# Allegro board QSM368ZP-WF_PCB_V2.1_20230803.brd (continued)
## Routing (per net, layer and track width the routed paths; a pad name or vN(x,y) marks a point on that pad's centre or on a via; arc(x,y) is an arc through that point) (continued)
N16421517: length 1.2
  TOP w0.3: R0730.2 D0706.2
N16421911: length 1.3
  TOP w0.3: D0705.2 R0708.2
N16451445: length 2.3
  BOTTOM w0.1: 38.48,21.57 R0610.2 38.4,20.6 R0622.2
N16756675: length 2.7
  BOTTOM w0.1: U0601.3 76.53,24.48 76.14,24.86 75.76,24.86 R0604.2
N16757889: length 2.3
  BOTTOM w0.2: R0614.2 69.1,24.3 69.28,24.48 69.28,25.5
N16762456: length 3.4
  BOTTOM w0.1: U0304.4 32.2,18.6 32.67,19.07 R0309.2 R0319.2 31.62,19.52 R0305.2
N16762522: length 2.1
  BOTTOM w0.1: R0308.2 R0313.2 32.2,16.02
N16784705: length 6.1
  BOTTOM w0.1: J0802.C2 70.14,18.96 69.53,19.57 69.53,21.07 69.22,21.38 D0803.3 68.25,21.38 C0806.2 67.97,21.4 R0803.2
N16784727: length 8.7
  BOTTOM w0.1: R0810.2 69.62,22.62 C0802.2 70.55,21.8 70.33,21.57 D0803.4 70.1,21.38 69.72,21 69.72,19.7 70.53,18.9 72.38,18.9 72.67,18.6 J0802.C3
N16784743: length 9.5
  BOTTOM w0.1: 73.94,17.83 73.94,18.61 73.42,19.12 70.6,19.12 69.92,19.8 69.92,20.77 70.03,20.88 D0803.5 C0804.2 R0804.1 73.03,20.88 R0808.2
N16788349: length 21.5
  TOP w0.8: J0801.P4 69.02,3.51 70.22,2.3 73.45,2.3 75.35,4.2 75.35,17.07
N16817948: length 2.2
  TOP w0.1: B1002.2 C1014.1 U1002.1
N16818791: length 2.8
  TOP w0.5: R1023.2 D1001.1 J1002.2
N16820129: length 0.8
  BOTTOM w0.23: U1001.5 12.31,63.77
N16820177: length 3.6
  BOTTOM w0.2: B1003.2 C1022.1 9.38,64.58 ; U1001.8 9.41,64.61 9.38,64.58 ; 9.38,64.58 9.38,65.42 R1016.1
N16820236: length 2.2
  BOTTOM w0.2: C1027.2 11.07,63.08 11.3,63.3 11.3,63.6 11.67,63.97 U1001.6
N16820242: length 2.7
  BOTTOM w0.2: C1022.2 10.07,63.75 10.8,63.75 11.04,63.99
  BOTTOM w0.23: U1001.7 11.04,63.99
N16820310: length 8.8
  BOTTOM w0.23: U1001.15 14.21,68.96
  BOTTOM w0.25: C1021.2 20.23,70.6 R1005.1 19.65,70.03 17.57,70.03 16.18,68.62 14.55,68.62 14.21,68.96
N16820326: length 2.2
  BOTTOM w0.23: U1001.14 13.58,70.55
  BOTTOM w0.25: 13.58,70.55 14.45,71.42 R1021.1
N16820338: length 3
  BOTTOM w0.23: U1001.13 12.94,70.82
  BOTTOM w0.25: 12.94,70.82 13.35,71.22 C1001.2 R1011.2
N16820356: length 4.1
  BOTTOM w0.23: U1001.12 12.31,70.77
  BOTTOM w0.25: 12.31,70.77 C1008.1 R1007.2 R1011.1
N16820452: length 3.7
  BOTTOM w0.23: U1001.10 11.04,68.71
  BOTTOM w0.25: 11.04,68.71 10.93,68.6 9.45,68.6 R1012.2 C1005.2
N16820458: length 4
  BOTTOM w0.23: U1001.11 11.67,70.68
  BOTTOM w0.25: R1008.1 9.7,71.38 10.05,71.03 11.32,71.03 11.67,70.68
N16820548: length 1.5
  BOTTOM w0.25: C1004.1 20.75,61.6 R1019.2
N16820558: length 0.9
  BOTTOM w0.23: U1001.4 12.94,63.73
N16820570: length 2.6
  BOTTOM w0.2: R1002.2 13.22,59.12 C1012.1
N16820612: length 2.1
  BOTTOM w0.2: C1011.1 11.43,59.2 11.62,59.4 R1020.2
N16820614: length 1.4
  BOTTOM w0.1: R1016.2 C1007.1
N16820628: length 1.9
  BOTTOM w0.25: R1008.2 8.9,73.25 9,73.35 10.45,73.35 C1017.2
N16820646: length 1.3
  BOTTOM w0.25: C1016.2 15.12,73.72 14.62,73.22
N16820759: length 3.8
  BOTTOM w0.25: C1026.2 16.05,62.05 15.28,62.83 15.28,63.5 15.03,63.75 14.46,63.75 14.21,64 U1001.2
N16820857: length 2.1
  BOTTOM w0.1: C1020.2 14.62,63.15 13.93,63.85 13.72,63.85 13.58,64 U1001.3
N16829674: length 1.5
  BOTTOM w0.1: C1111.1 U1103.2
N16829682: length 1.5
  BOTTOM w0.1: C1104.2 U1103.6
N16829803: length 1.3
  BOTTOM w0.1: U1103.10 R1120.1
N16830150: length 2.1
  BOTTOM w0.1: 102,66 102,66.5 102.2,66.7 R1134.2 R1111.2
N16830180: length 1.5
  BOTTOM w0.1: R1105.2 102.33,61.3 102.33,62.09 102.22,62.2 102,62.2
N16830190: length 7.2
  BOTTOM w0.1: Q1102.3 100.88,62.55 101.12,62.8 101.12,63.27 101.31,63.47 102,63.47 ; Q1102.3 Q1101.3 101.03,64.55 101.21,64.73 102,64.73 ; Q1102.3 R1103.1
N16831384: length 6.1
  BOTTOM w0.3: B0202.1 C0211.2 R0214.1
  BOTTOM w0.5: C0208.2 86.11,93.25 B0203.1 88.25,93.25 B0202.1
N16831443: length 4
  BOTTOM w0.3: B0204.1 B0201.1 C0212.2 77.6,92.1 78.47,91.22 U0203.5
N16831459: length 1.2
  BOTTOM w0.1: U0203.4 C0216.2
N16831535: length 4
  BOTTOM w0.4: 81.69,93.74 82.51,93.74 R0209.1 ; 81.69,93.74 R0229.1 ; 81.69,93.74 81.65,93.7 C0217.2 81.65,92.1 82.38,91.38 82.38,90.94
N16831549: length 1.2
  BOTTOM w0.1: 80.47,90.94 C0207.2
N16832505: length 2.9
  BOTTOM w0.1: C0299.2 R0212.1 R0219.2 U0205.4
N16833633:
  vias: v1(1.85,85.75) v1(1.85,85.25) v1(2.35,85.75) v1(2.35,85.25)
N16851360: length 2.8
  BOTTOM w0.4: B0501.1 B0502.1 C0526.2 U0501.5
N16851388: length 3.1
  BOTTOM w0.1: R0510.1 R0526.1 R0518.2 U0501.3
N16851406: length 1.1
  BOTTOM w0.1: C0511.1 U0501.4
N16851801: length 1.6
  BOTTOM w0.5: 64.58,71.92 66.22,71.92
N16851821: length 6
  BOTTOM w0.5: L0501.2 64,68.05 64.4,68.45 64.4,69.85 D0508.2
N16865312: length 6.5
  BOTTOM w0.1: R0949.1 R0947.2 100.2,40.52 101,41.33 101,42.02 101.9,42.92 U0902.14
N16865348: length 4.2
  BOTTOM w0.1: R0931.1 99.85,39.8 100.03,39.8 101.25,41.02 101.25,41.98 101.8,42.52 U0902.13
N16871216: length 3.4
  BOTTOM w0.1: R0913.1 108.97,39.9 108.47,40.4 108.47,40.65 108.25,40.88 108.25,41.42 107.55,42.12 U0902.39
N16979946: length 2.5
  BOTTOM w0.075: 104.62,57.12 104.25,57.12 U1102.C2
  BOTTOM w0.1: 104.62,57.12 104.72,57.12 104.8,57.2 R1107.1
  BOTTOM w0.25: R1132.1 R1107.1
N16980060: length 1
  BOTTOM w0.1: R1115.1 104.7,55.95 104.5,56.15 U1102.D3
N16980062: length 1.2
  BOTTOM w0.1: U1102.A3 103,56.35 R1130.2
N16980064: length 0.9
  BOTTOM w0.1: U1102.C3 104,55.98 103.85,55.83 R1126.2
N16980078: length 1.1
  BOTTOM w0.1: R1119.2 103,55.88 U1102.B3
N17169242: length 2.4
  TOP w0.1: v1(79.58,97) J0202.25
  BOTTOM w0.1: v1(79.58,97) R0227.1 R0226.2
N17248848: length 3
  TOP w0.3: U0502.5 C0524.2 C0528.1 21.38,98.4 B0503.1
N17248866: length 1.1
  TOP w0.1: C0514.1 U0502.4
N17269506: length 3.7
  TOP w0.1: R0515.1 13.53,93.55 14.15,94.17 14.8,94.17 15.22,93.75 15.22,92.81 U0503.3
N17270599: length 1.7
  TOP w0.3: R0513.2 C0535.2 16.1,92.03
N17274420: length 1.3
  TOP w0.1: v1(28.88,98.53) 29.07,98.33 J0501.7
  BOTTOM w0.1: v1(28.88,98.53) R0528.1
N17308117: length 5.8
  TOP w0.1: S1202.2 102.75,94.4 103.58,93.58 D1201.2 R1208.2
N17310824: length 1
  TOP w0.5: R0116.2 D0102.2
N17312479: length 2.6
  BOTTOM w0.1: R0104.1 R0101.1 27.55,83.58 27.55,84.12 27.7,84.28 27.98,84.28
N17312557: length 0.9
  BOTTOM w0.1: C0111.2 27.98,83.78
N17312561: length 2.7
  BOTTOM w0.1: 30.18,84.1 30.32,84.25 ; 30.18,84.1 30.18,84.35 ; 30.18,84.1 30.18,83.65 29.38,82.85 C0111.1 ; 30.18,84.1 30.07,84.2
N17312853: length 1.8
  BOTTOM w0.1: R0115.2 R0108.2 27.98,84.78
N17316601: length 3.6
  BOTTOM w0.1: R0166.1 R0113.1 R0103.2 51.38,84.55 51.38,85.15 51.48,85.25 U0103.5
N17316611: length 1.2
  BOTTOM w0.1: C0113.2 51.85,84.5 U0103.4
N17316621: length 3.5
  BOTTOM w0.1: 53.42,83.83 53.48,83.83 54,84.35 54,85.5 54.88,86.38 55.08,86.38 L0101.1
N17316661: length 1.9
  BOTTOM w0.1: R0105.2 R0114.1 U0103.6
N17321443: length 3
  BOTTOM w0.1: U0104.5 35.12,66.35 34.95,66.53 34.42,66.53 R0110.2 R0117.1
N17321453: length 0.9
  BOTTOM w0.1: U0104.4 C0114.2
N17321455: length 2.7
  BOTTOM w0.1: C0114.1 34.2,64.65 34.2,64.4 34.48,64.12 35.02,64.12 35.6,63.55
N17321503: length 1.9
  BOTTOM w0.1: R0102.2 R0112.1 U0104.6
N17391886: length 3.7
  BOTTOM w0.1: 35.83,49.92 35.83,50.23 36.08,50.48 R0620.1 R0615.2 36.92,50.45 37.02,50.35 37.92,50.35 38.1,50.17 U0604.5
N17391896: length 0.9
  BOTTOM w0.1: U0604.4 36.67,49.92
N17391898: length 2.5
  BOTTOM w0.1: 38.02,47.05 36.67,48.4 C0618.1
N17391938: length 1.7
  BOTTOM w0.1: U0604.6 38.62,49.95 R0613.1 R0606.2
N17593444: length 2.7
  BOTTOM w0.1: U1204.1 C1203.2 R1202.2 R1205.2
N17594281: length 1.2
  BOTTOM w0.1: U1204.9 C1204.2
N17594510: length 3.1
  BOTTOM w0.1: U1204.8 83.53,70.2 C1202.2 R1210.2 R1211.2
N17654307: length 5.4
  TOP w0.1: J0501.5 29.88,98.62 30.4,99.15 33.1,99.15 TP0502.1
N17980948: length 3.1
  BOTTOM w0.1: U0701.5 68.53,32.97 68.39,32.97 68.08,32.66 68.08,32.65 R0725.2 R0726.2 R0723.1
N17980958: length 1.3
  BOTTOM w0.1: C0714.2 69.03,32.23 68.83,32.42 U0701.4
N17980968: length 2.8
  BOTTOM w0.1: L0701.1 72.1,31.9 71.65,31.45 C0714.1
N17981000: length 2
  BOTTOM w0.1: R0717.1 R0718.2 67.75,33.83 68.15,33.42 U0701.6
N18035182: length 1.5
  BOTTOM w0.3: L0901.2 R0988.1
N18073365: length 2.7
  TOP w0.5: R1010.2 D1003.1 22.68,11.41 J1002.3
N18075719: length 5.7
  TOP w0.1: J1002.4 21.18,12.09 20.45,12.82 19.9,12.82 19.8,12.93 D1004.1 R1014.2
N18080454: length 3.8
  TOP w0.25: R1003.1 C1015.2 C1099.2 16.52,90.2 D1002.1 16.57,88.91 U1002.4
N18191565: length 8.2
  BOTTOM w0.1: R1117.2 100.97,68.03 98.35,65.4 R1121.2 Q1101.1
N18198024: length 1
  BOTTOM w0.1: R1125.1 Q1102.1
N18247329: length 11.2
  BOTTOM w0.3: R0426.2 9.22,17.25 R0420.2 7.55,17.6 7.78,17.82 7.78,18.32 7.12,18.98 5.24,18.98 4.85,19.36 4.85,22.15 6.08,23.38 D0402.1
N18365015: length 3.9
  TOP w0.5: D0405.1 C0412.1 C0408.1 R0402.2
N18366438: length 3.3
  BOTTOM w0.1: C0405.1 R0407.2 63.8,91.08 Q0401.1 64.35,91.88 64.83,92.35 Q0402.3
N18378711: length 3.7
  BOTTOM w0.1: D0507.3 18.2,33.4 18.05,33.55 C0517.1 R0529.2 16.18,33.55 15.93,33.3 Q0501.1
N18380308: length 6.4
  BOTTOM w0.1: R0503.2 6.28,44.17 5.8,43.7 C0516.1 ; R0503.2 7.47,44.17 7.58,44.27 Q0502.1 ; R0503.2 6.72,43.02 6.08,42.38 D0503.3
N18382144: length 2.2
  BOTTOM w0.1: 11.72,42.88 13.72,42.88 TP0503.1
N18382149: length 2.5
  BOTTOM w0.1: 9.32,53.38 8.03,53.38 TP0501.1
N18582530: length 241.3
  TOP w0.1: v1(98.6,69.53) 98.6,68.62 99.33,67.9 99.33,60 100.77,58.55 108.95,58.55 113.17,54.33 115.55,54.33 117.44,52.44 117.44,49.61 118.47,48.58 118.47,31.08 115.91,28.51 115.91,26.84 114.1,25.02 114.1,21.7 118.92,16.88 118.92,2.85 117.15,1.07 81.33,1.07 v1(80.05,2.35) ; U1301.171 23.38,47.48 v1(22.9,47.95) ; v1(60.3,2.38) 59.7,2.98 59.33,2.98 57.27,5.03 42.1,5.03 39.49,7.64 v1(39.49,7.94)
  INNER LAYER 3 w0.1: v1(22.9,47.95) 22.7,47.95 22.43,47.67 22.43,45.33 25.43,42.33 25.43,32.6 24.43,31.6 24.43,18.98 28.82,14.57 29.6,14.57 32.65,11.53 36.52,11.53 39.08,8.97 39.08,8.35 v1(39.49,7.94) ; v1(80.05,2.35) 79.42,2.98 60.58,2.98 60.3,2.7 v1(60.3,2.38) ; v1(82.03,73.65) 83.67,75.3 86.65,75.3 92.08,69.88 98.25,69.88 v1(98.6,69.53)
  BOTTOM w0.2: v1(82.03,73.65) R1301.1
N18603622: length 2.9
  TOP w0.1: U1301.231 39.75,32.27 39.95,32.08 40.08,32.08 41.38,30.77 41.42,30.77 TP1401.1
N18618933: length 1.1
  BOTTOM w0.2: R0416.2 D0401.1
N18646162: length 6.5
  TOP w0.1: TP1403.1 42.33,31.12 41.77,31.68 41.12,31.68 40.55,32.25 U1301.232
N18646180: length 6.2
  TOP w0.1: U1301.227 38.95,32.23 39.52,31.65 39.85,31.65 40.5,31 TP1404.1
N18646198: length 5.4
  TOP w0.1: TP1405.1 38.48,31.8 37.75,31.8 37.35,32.2 U1301.222
N18646284: length 4
  TOP w0.1: R1457.2 TP1402.1 36.55,32.23 U1301.221
N18671521: length 2.8
  BOTTOM w0.1: C0211.1 R0214.2 89.28,91 89.3,90.97 R0224.2 U0204.1
N18920153: length 3.4
  TOP w0.1: U1301.234 v1(42.15,37.7)
  BOTTOM w0.1: v1(42.15,37.7) 42.25,37.8 43.12,37.8 43.58,38.25 43.58,39.1
N18932423: length 1.7
  TOP w0.1: 38.92,29.52 38.92,27.82
N19051361: length 1.7
  BOTTOM w0.1: U1103.4 106.8,78.88 106.35,79.33 C1113.1
N19051366: length 1.6
  BOTTOM w0.1: C1113.2 107.25,79.3 107.45,79.1 U1103.5
N19051381: length 0.9
  BOTTOM w0.1: C1105.1 U1103.1
N19051390: length 3
  BOTTOM w0.1: U1103.3 106.15,77.4 106,77.25 C1105.2
N19051717: length 2.6
  BOTTOM w0.1: U1103.9 109.4,71.58 109.2,71.38 109.2,70.33 109.08,70.2 R1133.1
N19139644: length 3.2
  TOP w0.4: R0325.1 D0353.1 37.33,5.9 36.94,5.51 36.94,4.62
N19156624: length 2.7
  BOTTOM w0.1: R1155.2 R1156.1 101.83,58.08 102.1,57.8 102.3,57.8 102.72,57.38 U1102.A1
N19156735: length 2.4
  BOTTOM w0.1: R1157.2 R1158.1 104.4,58.1 104.17,57.88 104,57.88 U1102.B1
N19156807: length 2.7
  BOTTOM w0.1: U1102.C1 104.47,57.85 105.03,57.85 105.25,58.08 R1159.2 R1160.1
N19156822: length 3.7
  BOTTOM w0.1: U1102.D1 104.78,57.65 105.12,57.65 105.3,57.83 106.53,57.83 R1162.1 R1161.2
N19197680: length 2.5
  TOP w0.1: v1(41.25,38.58) U1301.229
  BOTTOM w0.1: v1(41.25,38.58) 41.85,38.58 41.88,38.6 R1467.1 R1466.1
N19332658: length 2.7
  TOP w0.1: J0701.17 TP0702.1
N19332747: length 2.3
  TOP w0.1: J0701.1 82.67,27.35 82.67,26.12 TP0703.1
N19347845: length 1.7
  BOTTOM w0.1: U0702.13 R0731.1
N19347847: length 1.8
  BOTTOM w0.1: R0729.1 95.4,59.6 95.2,59.4 U0702.12
N19347865: length 2.6
  BOTTOM w0.1: U0702.8 95.8,62 R0727.2 R0705.1
N19347930: length 2
  BOTTOM w0.1: U0702.2 87.45,58.75 86.9,58.2 R0713.2
N19349212: length 2
  BOTTOM w0.1: R0720.2 87.42,59.4 U0702.3
N19352428: length 1.7
  TOP w0.1: R0724.2 103.17,26.27 103.28,26.38 J0701.45
N19352448: length 1.7
  TOP w0.1: J0701.47 104.08,26.32 104.03,26.27 R0703.2
N19352470: length 1.7
  TOP w0.1: J0701.49 R0710.2
N19352490: length 1.7
  TOP w0.1: R0714.2 105.72,26.27 105.67,26.32 J0701.51
N19352717: length 1.8
  BOTTOM w0.1: R0711.1 C0706.2 D0703.3
N19354367: length 2.4
  TOP w0.1: R0701.2 94.47,25.18 J0701.23
N19354450: length 3.4
  TOP w0.1: J0701.31 97.67,25.12 97.28,24.73 R0704.2
N19356842: length 2.5
  TOP w0.1: J0701.33 R0706.2
N19357290: length 1.9
  TOP w0.3: J0701.24 R0728.1
N19357904: length 14
  TOP w0.1: J0701.32 98.08,30.6 v1(98.03,30.55) ; v1(93.53,24.95) TP0701.1
  INNER LAYER 3 w0.1: v1(93.53,24.95) 93.53,26.8 97.28,30.55 v1(98.03,30.55)
N19358667: length 2.4
  BOTTOM w0.1: R0721.2 87.28,60.92 87.53,60.67 87.53,60.3 87.78,60.05 U0702.4
N19358768: length 1.9
  BOTTOM w0.1: R0733.1 95.67,60.45 95.28,60.05 U0702.11
N19359275: length 9.2
  TOP w0.1: R0715.1 110.6,37.55 104.7,37.55 103.67,36.52 J0701.46
N19367635: length 1.9
  BOTTOM w0.1: U0702.10 95.35,60.7 R0722.1
N193479154: length 4.8
  BOTTOM w0.1: U0702.5 89.85,60.7 90.08,60.92 90.08,62.48 89.22,63.33 R0712.2

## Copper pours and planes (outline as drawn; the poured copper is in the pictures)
AVDD33_A on BOTTOM: 106.88,41.62 107.33,41.62 107.58,41.38 107.58,40.23 108.08,40.23 108.12,40.27 108.12,40.77 108.04,40.86 108.04,41.41 107.62,41.83 106.78,41.83 106.78,41.73
DVDDRG_A on BOTTOM: 105.78,46.02 105.78,46.45 105.85,46.52 105.85,47.45 105.53,47.77 105.38,47.77 105.22,47.62 105.22,47.3 105.53,47 105.53,46.35 105.58,46.3 105.58,46.05 105.6,46.02
VBATT on TOP: 15.88,86.12 17.45,86.12 17.7,86.38 18.35,86.38 18.52,86.2 18.52,84.7 18.4,84.58 17.73,84.58 17.48,84.83 15.88,84.83
VBATT on TOP: 75.12,85.88 75.72,85.28 75.72,84.7 75.25,84.22 74.72,84.22 73.88,85.08 73.88,85.4 74.35,85.88
VBATT on TOP: 46.58,77.28 50.2,77.28 51.75,78.83 51.75,79.95 51.42,80.28 48.08,80.28 45.88,82.47 37.42,82.47 35.52,80.58 35.52,79.15 35.62,79.05 36.48,79.05 36.8,79.38 44.48,79.38
VBATT on TOP: 69.28,84.55 66.83,84.55 65.95,83.67 65.95,82.75 67.2,81.5 68.03,81.5 69.28,82.75
VBATT on TOP: 15.2,92.17 15.03,92.17 14.9,92.3 13.28,92.3 13.15,92.17 13.15,91.85 13.25,91.75 15.22,91.75 15.35,91.88 15.35,92.03
VBATT on TOP: 61.08,77.85 58.92,77.85 58.67,78.1 58.67,80.12 59.38,80.83 61,80.83 61.42,80.4 61.42,78.2
VBATT on BOTTOM: 87.97,89.6 88.83,89.6 89.03,89.8 89.55,89.8 89.55,88.67 88.75,88.67 88.75,89.28 88.72,89.3 87.97,89.3
VBATT on BOTTOM: 31,80.58 36.42,80.58 36.52,80.47 36.52,78.15 35.6,77.22 31,77.22 30.88,77.35 30.88,80.45
VBATT on BOTTOM: 62.05,70.35 61.45,70.35 61.05,70.75 61.05,71.75 60.38,71.75 60.35,71.72 60.35,70.78 59.98,70.4 59.17,70.4 59.17,69.7 62.05,69.7
VBATT on BOTTOM: 21.07,83.62 21.07,80.9 24.75,77.22 27,77.22 27.95,78.17 27.95,78.6 22.93,83.62
VBATT on BOTTOM: 50.3,79.9 50.3,77.62 50.65,77.28 52.15,77.28 52.62,77.75 52.62,79.95 52.3,80.28 50.67,80.28
VBATT on BOTTOM: 59.67,79.83 59.67,78.03 58.77,77.12 58.1,77.12 57.5,77.72 57.5,80.05 57.73,80.28 59.23,80.28
VBATT on BOTTOM: 75.12,85.88 75.85,85.15 75.85,84.7 75.42,84.28 74.5,84.28 74.05,84.72 74.05,85.3 74.62,85.88
VBATT_M on TOP: 15.88,83.33 16.15,83.6 19.77,83.6 19.93,83.45 19.93,82.12 19.55,81.75 17.75,81.75 17.48,82.03 15.88,82.03
VBATT_M on TOP: 23.45,54.23 24.55,54.23 25.35,55.02 26.45,55.02 27.25,54.23 28.25,54.23 28.25,51.92 27.15,51.92 26.35,51.12 25.25,51.12 24.45,50.33 23.45,50.33
VBATT_M on BOTTOM: 24.27,52.08 22.52,53.83 22.52,61.27 22.55,61.3 22.55,64.17 22.88,64.5 22.88,67.8 22.55,68.12 22.55,74.25 17.85,78.95 17.85,80.88 18.45,81.47 18.45,83.28 19.02,83.85 19.85,83.85 20.45,83.25 20.45,80.88 25.85,75.47 25.85,68.03 26.18,67.7 26.18,64.45 25.75,64.03 25.75,61.45 25.65,61.35 25.65,52.2 25.52,52.08
VBUS_USB_HOST1 on TOP: 39.95,16.5 39.95,13.25 41.02,13.25 41.25,13.03 41.62,13.03 41.62,13.55 41.1,14.07 40.88,14.07 40.8,14.15 40.8,16.23 41.08,16.5 41.08,16.85 40.9,17.02 40.48,17.02
VBUS_USB_HOST1 on BOTTOM: 40.1,21.98 42.15,21.98 42.17,21.95 42.17,19.48 42.05,19.35 40.12,19.35 40.1,19.38
VBUS_USB_HOST2 on TOP: 80.42,17.75 80.42,19.52 79.8,20.15 79.3,20.15 78.83,20.62 78.83,21.15 79,21.32 80.8,21.32 82.15,19.98 82.92,19.98 82.92,17.98 82.83,17.98 82.6,17.75
VBUS_USB_HOST2 on BOTTOM: 78.15,25.95 79.85,25.95 80.15,25.65 80.15,23.8 79.7,23.35 78.15,23.35
VBUS_USB_HOST2 on BOTTOM: 78.95,21.45 79.9,21.45 80.1,21.25 80.1,20.93 79.65,20.48 79.05,20.48 78.8,20.73 78.8,21.3
VBUS_USB_HOST3 on TOP: 80.65,12.72 80.65,15.9 81.62,15.9 81.62,13.03 81.33,12.72
VBUS_USB_HOST3 on TOP: 73.42,23.35 72.65,23.35 72.42,23.57 72.42,23.98 72.7,24.25 73.38,24.25 73.6,24.02 73.6,23.52
VBUS_USB_HOST3 on BOTTOM: 70.9,25.9 72.8,25.9 72.95,25.75 72.95,24.25 73.45,23.75 73.45,23.5 73.3,23.35 70.9,23.35
VCC3V3_SD on TOP: 50.5,35.27 50.5,34.23 50.55,34.17 50.83,34.17 50.95,34.05 50.95,33.8 50.83,33.67 50.05,33.67 49.8,33.92 49.8,35.27
VCC3V3_SD on INNER LAYER 2: 50.45,33.3 50.95,33.8 50.95,34.05 50.83,34.17 50.08,34.17 49.8,33.9 49.8,33.48 49.98,33.3
VCC5V0_SYS on TOP: 23.45,46.23 24.45,46.23 24.68,46.45 25,46.45 25.25,46.2 25.43,46.2 25.57,46.05 25.57,45.77 25.4,45.6 25.18,45.6 25,45.42 24.55,45.42 24.45,45.52 23.45,45.52
VCC5V0_SYS on BOTTOM: 26.32,46.17 25.77,46.17 25.5,46.45 24.75,46.45 24.62,46.33 24.62,45.52 24.85,45.3 26,45.3 26.32,45.62
VCC5V0_USB on TOP: 70.38,27.1 70.95,27.68 71.85,27.68 72.4,27.12 72.4,26.57 71.7,25.88 70.6,25.88 70.38,26.1
VCC5V0_USB on TOP, BOTTOM: 63.02,27.38 64.45,27.38 64.55,27.27 64.55,26.15 64.28,25.88 62.95,25.88 62.65,26.18 62.65,27
VCC5V0_USB on BOTTOM: 30.62,45.27 30.62,37.23 33.65,37.23 33.65,46.38 31.73,46.38
VCC5V0_USB on BOTTOM: 42.17,22.75 40.83,22.75 40.1,23.48 40.1,24.3 42.05,24.3 42.17,24.18
VCC5V0_USB on BOTTOM: 34.65,26 34.65,30.82 34.95,31.12 37.3,31.12 37.7,30.73 37.7,26.57 37.12,26
VCC5V0_USB on BOTTOM: 35.85,17 34.73,17 33.83,17.9 33.83,18.7 35.62,18.7 35.85,18.48
VCC5V0_USB on BOTTOM: 70.9,28.2 72.78,28.2 72.9,28.07 72.9,26.5 71.22,26.5 70.9,26.82
VCC5V0_USB on BOTTOM: 78.15,28.25 80.15,28.25 80.15,26.43 79.17,26.43 78.15,27.45
DC12V on TOP: 3.17,44.7 3.42,44.7 4.05,45.33 4.05,45.58 3.6,46.02 3.5,46.02 3.05,45.58 3.05,44.83
DC12V on TOP: 9.8,82.83 10.95,82.83 11.07,82.7 11.07,82.47 10.28,81.67 9.75,81.67 9.55,81.88 9.55,82.58
DC12V on TOP: 39.83,88.03 43.58,88.03 44.48,87.12 49.1,87.12 49.7,87.72 49.7,87.9 49.83,88.03 51.1,88.03 51.25,87.88 51.25,84.65 50.58,83.97 39.83,83.97
DC12V on TOP: 26,88.6 23.25,88.6 22.4,87.75 22.4,85.88 24.27,84 26.62,84 26.62,87.97
DC12V on BOTTOM: 38.45,48.8 38.85,48.8 39.62,49.58 39.62,51.8 40.08,52.25 42.17,52.25 42.17,49.77 42.58,49.38 42.58,48 39.67,48 39.48,48.2 38.55,48.2 38.45,48.3
DC12V on BOTTOM: 54.02,88.3 54.02,86.2 53.42,85.6 52.98,85.6 52.38,86.2 49.92,86.2 49.7,86.42 49.7,88.25 49.75,88.3
DC12V on BOTTOM: 69.58,33.65 68.8,34.42 64.33,34.42 63.27,33.38 61.2,33.38 61.2,35.55 62.27,36.62 68.92,36.62 70.53,35.02 70.53,33.65 70.15,33.27 69.7,33.27 69.58,33.4
DC12V on BOTTOM: 39.38,63.85 36.1,63.85 35.48,64.47 35.48,64.92 36,64.92 36.08,65 36.08,70.1 39.08,70.1 39.08,65.7 39.38,65.4
DC12V on BOTTOM: 39.33,40.45 37.12,40.45 36.27,39.6 36.27,35.83 38.08,34.02 38.08,30.12 40.1,28.1 43.3,28.1 43.3,31.1 42.48,31.1 41.55,32.02 41.55,34.3 41,34.85 41,35.2 39.85,36.35 39.85,39.92
DC12V on BOTTOM: 4,46.85 5.17,46.85 5.28,46.95 6.08,46.95 6.08,45.67 6.4,45.35 7,45.35 7,44.8 3.65,44.8 3.55,44.7 3.17,44.7 3.05,44.83 3.05,45.58 3.17,45.7 3.65,45.7 4,46.05
DC12V on BOTTOM: 40,74.9 40,84.75 40.4,85.15 42.65,85.15 43,84.8 43,74.9
DC12V on BOTTOM: 14.72,69.12 14.72,70.53 15.38,70.53 15.85,71 15.85,76.9 14.8,77.95 14.8,78.68 14.57,78.9 6.22,78.9 6.22,83.6 7.05,84.42 11.62,84.42 15.53,88.33 24.32,88.33 25.55,87.1 29.55,87.1 29.55,84.62 29.1,84.62 28.27,85.45 25.62,85.45 24.6,84.42 18.23,84.42 17.32,83.53 17.32,78.62 17.95,78 17.95,70.5 17.35,70.5 15.97,69.12
DC12V on BOTTOM: 40.7,64.08 40.7,62.58 42.2,61.08 42.2,59.85 41.48,59.12 39.62,59.12 37.9,60.85 37.9,63.17 36.73,64.35 36.73,65.17 36.92,65.38 39.4,65.38
EDP_VDDIN on BOTTOM: 8.53,39.58 10.43,39.58 10.93,40.08 12.55,40.08 14.11,38.51 14.11,36.41 14.78,35.75 14.9,35.75 14.9,34.83 14.55,34.48 12.62,34.48 12.57,34.42 11.82,34.42 11.8,34.45 11.8,35.45 11.9,35.45 12.28,35.83 12.28,37.77 11.9,38.15 8.75,38.15 8.53,38.38
EDP_VLED on BOTTOM: 8.65,52.58 7.53,52.58 7.05,52.1 7.05,49.35 6.65,48.95 4.6,48.95 4,48.35 4,47.65 4.8,47.65 4.8,47.92 4.92,48.05 7.05,48.05 7.95,48.95 7.95,51.6 8.65,52.3
ETH_3V3_A on BOTTOM: 89.95,43.62 92.5,43.62 92.5,43.08 91.8,43.08 91.65,42.92 91.65,40.83 90.83,40.83 89.95,41.7
LVDS_VDD3V3 on BOTTOM: 62.33,92.45 62.88,92.45 62.98,92.35 63.92,92.35 63.92,92.8 63.08,92.8 62.88,93 62.33,93
MODULE_4G_3V5 on TOP: 83.17,36.75 83.17,34.65 83.62,34.2 83.62,32.98 83.58,32.92 80.97,32.92 80.65,33.25 80.65,34.38 80.97,34.7 82.53,34.7 82.58,34.75 82.58,36.75
MODULE_4G_3V5 on TOP: 101.85,24.73 101.9,24.73 102.2,25.02 102.2,26.2 101.97,26.43 100.6,26.43 100.58,26.4 100.58,24.75 100.65,24.68 101.8,24.68
MODULE_4G_3V5 on BOTTOM: 76.72,30.7 76.72,36.48 77.35,37.1 83.58,37.1 84.55,36.12 84.55,31.9 84.53,31.88 83.28,31.88 82.2,32.95 80.72,32.95 78.47,30.7
REGOUT_A on BOTTOM: 106.85,48.42 106.85,47.3 106.55,47 106.55,46.52 106.38,46.35 106.38,46.17 106.58,46.17 106.6,46.2 107.12,46.2 108.65,47.73 108.65,48.42
SPK_OUT_LN on BOTTOM: 8.53,63.4 8.53,61.9 8.45,61.83 7.62,61.83 7.62,63.4
SPK_OUT_LP on BOTTOM: 10.6,60.77 8.75,60.77 8.75,60.08 10.6,60.08
USB_VBUS on TOP: 35.17,5.35 34.55,5.35 34.38,5.53 33.77,5.53 33.42,5.88 33.42,6.55 33.58,6.7 34.1,6.7 34.1,6.2 34.2,6.1 34.73,6.1 35.17,5.65
USB_VBUS on TOP: 33.1,13.97 33.1,11.12 33.12,11.1 34.48,11.1 35.17,11.8 35.17,14.25 35,14.43 33.55,14.43
USB_VBUS on TOP: 40.02,12.93 40.88,12.93 41.52,12.28 41.52,11.68 40.62,10.78 38.88,10.78 38.6,11.05 38.6,11.47 38.8,11.68 39.5,11.68 39.9,12.07 39.9,12.8
USB_VBUS on BOTTOM: 33.83,16.43 35.65,16.43 35.85,16.23 35.85,14.5 35.2,13.85 33.3,13.85 33.3,15.22 33.83,15.75
VDC_3V3 on TOP: 78.97,5.5 77.95,5.5 77.7,5.25 77.7,4.8 78,4.5 78.97,4.5 79.12,4.65 79.12,5.35
VDC_3V3 on TOP: 69.75,88.35 67.92,88.35 67.92,89.05 69.7,89.05 69.75,89
VDC_3V3 on TOP: 101.2,74.85 108.83,74.85 110.08,73.6 108.3,71.83 101.05,71.83 100.9,71.97 100.9,74.55
VDC_3V3 on TOP: 93.5,40.2 94.08,40.2 94.25,40.38 94.25,41.08 93.95,41.38 93.3,41.38 92.95,41.02 92.95,40.75
VDC_3V3 on TOP: 109.78,60.62 111.33,60.62 111.83,60.12 111.83,58.23 111.42,57.83 110.45,57.83 109.78,58.5
VDC_3V3 on TOP: 59.6,81.58 59.6,89.45 60.17,90.03 62.02,90.03 62.6,89.45 62.6,82.38 61.5,81.28 59.9,81.28
VDC_3V3 on TOP: 100.22,74.1 100.22,72.6 100.97,71.85 102.3,71.85 102.65,72.2 102.65,74.55 102.35,74.85 100.97,74.85
VDC_3V3 on TOP: 105.17,52.58 105.6,52.58 105.88,52.3 105.88,51.62 105.7,51.45 105.08,51.45 104.88,51.65 104.88,52.27
VDC_3V3 on TOP: 112.3,66.33 109.67,66.33 109.3,65.95 109.3,64.83 109.97,64.15 112.3,64.15
VDC_3V3 on TOP: 117.38,2.92 117.95,2.92 118.08,2.8 118.08,2.23 117.78,1.93 117.3,1.93 117.05,2.17 117.05,2.6
VDC_3V3 on BOTTOM: 59.8,84.78 59.8,88.58 57.65,90.72 57.65,91.95 61.2,91.95 61.2,92.1 62,92.1 62,90.75 62.27,90.47 62.27,85.33 61.73,84.78
VDC_3V3 on BOTTOM: 101.4,74.38 102.4,74.38 102.55,74.22 102.55,73.03 102.4,72.88 101.42,72.88 101.05,73.25 101.05,74.03
VDC_3V3 on BOTTOM: 92.15,41.83 92.15,40.9 92.42,40.9 92.95,40.38 93.22,40.38 93.42,40.17 94.1,40.17 94.2,40.27 94.2,40.58 92.95,41.83
VDC_3V3 on INNER LAYER 3: 117.33,2.02 117.88,2.02 118.22,2.38 118.22,2.83 117.95,3.1 117.55,3.1 117.22,2.77 117.22,2.12
VDC_3V3 on INNER LAYER 3: 101.6,74.38 102.53,74.38 102.65,74.25 102.65,73 102.53,72.88 101.53,72.88 101.17,73.22 101.17,73.95
VDC_3V3 on INNER LAYER 3: 118.22,50.4 118.62,50.4 118.9,50.12 118.9,49.45 118.75,49.3 118.08,49.3 117.9,49.48 117.9,50.08
VDC_3V3 on INNER LAYER 3: 59.8,82.1 59.8,80.47 60.73,79.55 62.05,79.55 62.8,80.3 62.8,81.72 61.98,82.55 60.25,82.55
VDC_3V3 on INNER LAYER 3: 110.53,58.77 111.25,58.77 111.58,58.45 111.58,58.08 111.28,57.77 110.65,57.77 110.38,58.05 110.38,58.62
VDC_3V3 on INNER LAYER 3: 105.15,51.58 105.58,51.58 105.9,51.9 105.9,52.35 105.62,52.62 105.15,52.62 104.9,52.38 104.9,51.83
VDC_5V on BOTTOM: 8.28,26.9 8.28,23 8.3,22.98 10.05,22.98 10.22,23.15 10.22,26.55 9.88,26.9
VDC_5V on BOTTOM: 33.6,58.05 37.02,58.05 37.62,57.45 37.62,55.05 37.35,54.77 33.6,54.77
VDC_5V on BOTTOM: 29.15,46.65 27.15,46.65 26.68,46.17 26.68,45.48 27,45.15 28.5,45.15 29.15,45.8
N16788349 on TOP: 75.75,20.88 75.75,16.62 75.6,16.48 74.95,16.48 74.95,20.82 75,20.88
N16820129 on BOTTOM: 9.7,62.27 10.88,62.27 10.97,62.38 11.38,62.38 11.78,62.77 11.78,63.48 12.12,63.83 12.12,63.92 12.2,64 12.4,64 12.47,63.92 12.47,62.5 12.28,62.3 12.28,61.48 9.8,61.48 9.7,61.58
N16820177 on BOTTOM: 10.53,64 10.53,65.4 9.8,66.12 8.47,66.12 8.45,66.1 8.45,65.35 8,64.9 7.62,64.9 7.62,64.2 7.83,64
N16820536 on BOTTOM: 14.72,64 14.72,65.22 15.65,65.22 15.82,65.05 15.82,64.45 17.7,62.58 19.07,62.58 19.07,61.27 17.2,61.27 16.68,61.8 16.68,62.25 16.45,62.48 16.23,62.48 15.55,63.15 15.55,63.55 15.1,64
N16820558 on BOTTOM: 12.82,64 13.05,64 13.47,63.58 13.47,62.85 14.15,62.17 15.15,62.17 15.15,61.58 15.05,61.48 12.6,61.48 12.6,62.38 12.78,62.55 12.78,63.85 12.82,63.9
N16831384 on BOTTOM: 86.03,90.35 84.17,90.35 84.17,92.22 85.6,92.22 86.22,91.6 86.22,90.8 86.42,90.6 87.17,90.6 87.17,90.3 86.08,90.3
N16833633 on BOTTOM: 4.7,79.25 4.7,84.37 3.95,85.07 3.95,90.42 3.02,91.35 1.82,91.35 0.93,90.45 0.93,79.92 1.6,79.25
N16833633 on INNER LAYER 3: 1.38,91.08 3.3,91.08 4.05,90.33 4.05,84.97 3.83,84.75 1.77,84.75 0.93,85.6 0.93,90.62
N16851801 on BOTTOM: 67.8,71.47 65.55,71.47 65.55,72.35 65.58,72.38 66.88,72.38 67.17,72.67 67.17,72.88 67.8,72.88
N16851821 on BOTTOM: 63.1,70.35 63.95,70.35 64.03,70.42 65.12,70.42 65.12,69.62 63.17,69.62 63.1,69.7
N17312561 on BOTTOM: 29.1,84.42 29.8,84.42 31.57,86.2 34.92,86.2 34.95,86.17 34.95,84.35 31.45,84.35 31.23,84.12 29.1,84.12
N17316621 on BOTTOM: 52.98,85.4 53.42,85.4 54.25,86.22 54.25,88.17 56.1,88.17 56.1,84.78 53.75,84.78 53.42,85.1 52.98,85.1
N17321455 on BOTTOM: 34.98,64.92 34.98,64.33 34.48,63.83 34.48,63.8 34.27,63.6 33.6,63.6 33.6,61.75 33.62,61.73 36.9,61.73 36.98,61.8 36.98,63.65 36.1,63.65 35.27,64.47 35.27,64.92
N17391898 on BOTTOM: 37.95,48.8 37.95,48.15 37.75,47.95 37.33,47.95 37.33,42.98 39.2,42.98 39.2,47.83 39.08,47.95 38.45,47.95 38.25,48.15 38.25,48.8
N17980968 on BOTTOM: 70.9,34.08 70.67,33.85 70.67,33.48 70.28,33.08 69.7,33.08 69.7,32.77 70.22,32.77 71.17,31.82 71.17,30.68 73.03,30.68 73.03,34.08
N18035182 on BOTTOM: 106.85,49.23 108.65,49.23 108.65,50.12 108.58,50.2 108.58,51.85 108.75,52.02 109.3,52.02 109.35,52.08 109.35,52.67 107.78,52.67 107.78,50.27 107.53,50.02 106.95,50.02 106.85,49.92
N18365015 on TOP: 72.95,88.85 73.05,88.85 73.5,89.3 73.5,92.28 73.67,92.45 74.22,92.45 74.4,92.28 74.4,89.3 74.85,88.85 74.95,88.85 74.95,87.75 72.95,87.75
N18365073 on TOP: 70.8,88.35 70.8,89.9 70.9,90 73,90 73,89.3 72.9,89.3 72.45,88.85 72.45,87.75 71.65,87.75 71.05,88.35
N18670938 on BOTTOM: 87.17,89.6 86.08,89.6 86.03,89.55 84.17,89.55 84.17,88.85 85.97,88.85 86.42,89.3 87.17,89.3

Small or netless copper shapes (teardrops, artwork), in the pictures only: 8 on TOP, 5 on BOTTOM, 2 on INNER LAYER 2, 4 on INNER LAYER 3

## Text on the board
BOTTOM: QSM368ZP-WF_V2.1_BOTTOM
Package Geometry/Pastemask Bottom: QSM368ZP-WF_V2.1_PASTEMASK_BOTTOM
Ref Des/Silkscreen Bottom: 5V | 3V3 | BATTERY | 5G-SIM | eDP | QSM368ZP-WF_V2.1_SILKSCREEN_BOTTOM
User.Comments: QSM368ZP-WF_V2.1_SOLDERMASK_BOTTOM | QSM368ZP-WF_V2.1_SOLDERMASK_TOP
TOP: QSM368ZP-WF_V2.1_TOP
Package Geometry/Pastemask Top: QSM368ZP-WF_V2.1_PASTEMASK_TOP
Ref Des/Silkscreen Top: SPK | GND | N | P | RN | RP | LN | LP | HDMI | MIC | HEADSET | WIFI/BT | LCD | USB_OTG | MENU | ESC | LCD_TP | RST | VOL_DOWN | LVDS_TP | TYPE-A 3.0 | QSM368ZP-WF_V2.1 | LVDS | SD | CAM1 | TYPE-A 2.0 | CAM0 | PWRKEY | GMAC1_RJ45 | ON | OTG | HOST | OFF | VBAT | DC_12 | PON_1 | QSM368ZP-WF_V2.1_SILKSCREEN_TOP
INNER LAYER 2: QSM368ZP-WF_V2.1_INNER LAYER 2
INNER LAYER 3: QSM368ZP-WF_V2.1_INNER LAYER 3
DEVICE_TYPE_TOP: FIGURE | SIZE | 0.25 | 0.7 | 0.8 | 0.85 | 0.9 | 0.92 | 1.0 | 1.02 | 1.2 | 1.4 | 1.8 | 2.3 | 2.5 | 3.15 | 1.1 | 1.3 | 1.6 | 2.4 | 3.35 | 1.2x0.5 | 1.4x0.8 | 1.7x0.8 | 2.1x0.6 | 2.6x0.8 | 3.1x0.8 | DRILL CHART: TOP to BOTTOM | ALL UNITS ARE IN MILLIMETERS | PLATED | NON-PLATED | QTY | 2768 | 18 | 23 | 1 | 5 | 8 | 4 | 2 | 6 | 3
